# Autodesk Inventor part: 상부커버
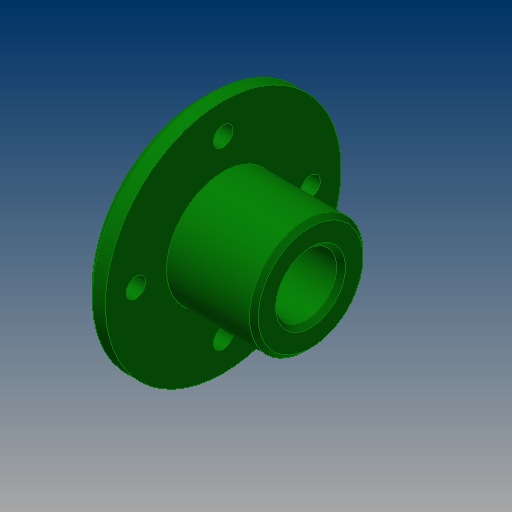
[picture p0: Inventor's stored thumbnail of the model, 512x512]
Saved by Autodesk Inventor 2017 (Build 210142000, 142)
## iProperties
Created: 2015-09
Part Number: 상부커버
Material: 알루미늄 6061
Document SubType Name: Modeling
Designer: mduedu
Density: 1 g/cm^3
Appearance: 진녹색
Author: mduedu
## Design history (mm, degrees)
sketch "스케치1"
  geometry: L1 (-12.5, 0)-(12.5, 0); L2 (-12.5, 0)-(-12.5, 27); L3 (-12.5, 27)-(-7.5, 27); L4 (-7.5, 27)-(-7.5, 13); L5 (-7.5, 13)-(12.5, 13); L6 (12.5, 13)-(12.5, 0); 2 further points
  constraints: 12 end point, 2 parallel, 2 perpendicular, 1 coincident, 1 horizontal, 1 midpoint, 1 vertical
  dimensions: "d0" = 25 distance of L1.start L1.end; "d2" = 5 distance of L2.end L3.end; "d3" = 26 diameter of L5 L1; "d4" = 54 diameter of L3 L1
revolve "회전1" sketch "스케치1" stored, may be unused: angle "d5" = 90 deg
hole "구멍1" diameter "d8" = 14; stored, may be unused: countersink angle "d12" = 90 deg, drill point angle "d14" = 118 deg; dims "d6" = 10, "d7" = 10, "d9" = 6, "d10" = 4, "d11" = 2, "d13" = 8
chamfer "모따기1" distance "d15" = 1; stored, may be unused: second distance "d16" = 2, angle "d17" = 45 deg
chamfer "모따기2" distance "d18" = 2; stored, may be unused: second distance "d19" = 2, angle "d20" = 45 deg
sketch "스케치2" dims "d21" = 40
  geometry: 6 further points
  constraints: 2 vertical alignment, 1 coincident, 7 other
  dimensions: "d25" = 360 deg dimension on point (0, 0) point (0, 20) (derived)
sketch "스케치3"
  geometry: 4 further points
hole "구멍2" sketch "스케치3" at (0, 20), (-20, 0), (20, 0), (0, -20) diameter "d27" = 4.5; stored, may be unused: countersink angle "d31" = 90 deg, drill point angle "d33" = 0 deg; dims "d28" = 6, "d29" = 4, "d30" = 2, "d32" = 8
chamfer "모따기3" distance "d34" = 1; stored, may be unused: second distance "d35" = 2, angle "d36" = 45 deg
node "솔리드1"
